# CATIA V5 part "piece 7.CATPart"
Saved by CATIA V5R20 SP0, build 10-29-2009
Part number: piece 7
Bounding box of the stored display mesh (mm): x -19.994 to 19.994, y -135 to 19.99, z 0 to 10
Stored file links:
  D:\Dropbox\IAO_2011\MMS_GR1\jdubreuilr\jdubreuilr\jdubreuilr\piece 7.CATPart
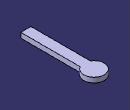
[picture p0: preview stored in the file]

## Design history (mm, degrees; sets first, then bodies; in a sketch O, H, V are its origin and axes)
Set1
  Point1: (0, 0, 0)
  Line1: type Normal, RefPoint Point1, RefSkin end face of Pad1, Start 0, End 20
Body1 (main body)
  Sketch1 on xy-plane, origin (0, 0, 0), H (1, 0, 0), V (0, 1, 0)
    line L1 (-10, -17.3205) -> (-10, -135)
    point P1 (-10, -17.3205)
    line L2 (10, -17.3205) -> (10, -135)
    point P3 (10, -17.3205)
    point P4 (10, -135)
    arc A1 centre (0, 0) radius 20 from (10, -17.3205) to (-10, -17.3205) ccw
    point P5 (-10, -17.3205)
    point P6 (10, -17.3205)
    line L3 (10, -135) -> (-10, -135)
    radius A1 = 20
    distance L1 V = 10
    distance L2 V = 10
    distance H P4 = 135
    vertical: L1 V, L2 V
    coincidence: P5 L1, P6 L2, P3 P6, P1 P5
    horizontal: L3 H
  Pad1: profile Sketch1, direction (0, 0, 1), length 10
